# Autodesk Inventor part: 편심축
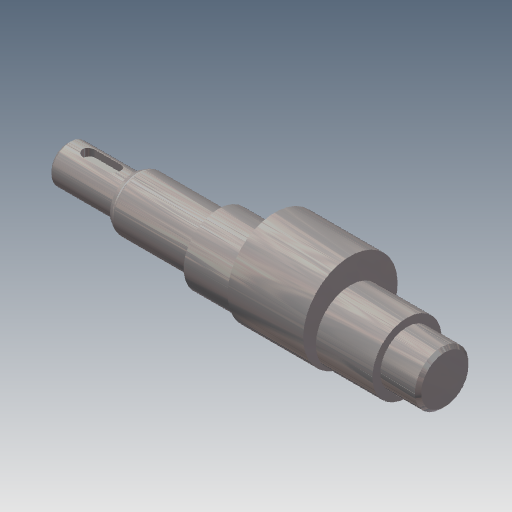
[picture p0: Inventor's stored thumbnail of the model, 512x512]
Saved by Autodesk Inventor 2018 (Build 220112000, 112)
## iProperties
Created: 2019-01
Part Number: 편심축
Material: 강철, 연강
Document SubType Name: Modeling
Designer: mduedu
Density: 7.86 g/cm^3
Appearance: 강철
Mass: 326.79 g
Surface Area: 90.9817 cm^2
Volume: 41.5764 cm^3
Author: mduedu
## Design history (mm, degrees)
sketch "스케치1"
  geometry: L1 (0, 0)-(21, 0); L2 (21, 0)-(21, 6); L3 (21, 6)-(0, 6); L4 (0, 6)-(0, 0); L5 (21, 0)-(48, 0); L6 (48, 0)-(48, 8.5); L7 (48, 8.5)-(21, 8.5); L8 (21, 8.5)-(21, 0); L9 (48, 0)-(108, 0); L10 (108, 0)-(108, 11); L11 (108, 11)-(48, 11); L12 (48, 11)-(48, 0); L13 (108, 0)-(120, 0); L14 (120, 0)-(120, 8.5); L15 (120, 8.5)-(108, 8.5); L16 (108, 8.5)-(108, 0)
  constraints: 32 end point, 8 parallel, 4 horizontal, 4 perpendicular
  dimensions: "d0" = 120 distance between parallel lines of L14 L4; "d2" = 12 distance of L14.end L15.end; "d3" = 60 distance of L10.end L11.end; "d4" = 99 distance between parallel lines of L8 L14; "d5" = 12 diameter of L3 L1; "d6" = 17 diameter of L7 L5; "d7" = 17 diameter of L15 L13; "d8" = 22 diameter of L11 L9
revolve "회전1" sketch "스케치1" stored, may be unused: angle "d9" = 90 deg
node "작업 평면1"
sketch "스케치2"
  geometry: C1 r 15 at (0, 4); C2 r 11 at (0, 0) reference; 1 further point
  constraints: 1 centre point, 1 tangent, 1 vertical alignment
  dimensions: "d11" = 4 distance of point (0, 0) C1.centre
extrude "돌출1" join sketch "스케치2" distance "d12" = 24; taper "d13" = 0 deg
node "작업 평면2"
sketch "스케치3" dims "d16" = 12
  geometry: L1 (-4.5, 2)-(3.5, 2); L2 (3.5, 2)-(3.5, -2); L3 (3.5, -2)-(-4.5, -2); L4 (-4.5, -2)-(-4.5, 2); L5 (-10.5, 8.5)-(-10.5, -8.5) reference; 3 further points
  constraints: 8 end point, 2 midpoint, 2 parallel, 2 vertical alignment, 1 horizontal, 1 horizontal alignment, 1 perpendicular, 4 other
  dimensions: "d14" = 4 distance between parallel lines of L3 L1; "d17" = 4 dimension on L5
extrude "돌출2" cut sketch "스케치3" distance "d18" = 2.5; taper "d19" = 0 deg
chamfer "모따기1" distance "d20" = 1.82; stored, may be unused: second distance "d21" = 2, angle "d22" = 30 deg
fillet "모깎기1" dims "d23" = 2
hole "구멍2" diameter "d39" = 3.242; stored, may be unused: countersink angle "d43" = 60 deg, drill point angle "d45" = 118 deg; dims "d37" = 10, "d38" = 10, "d40" = 8, "d41" = 5.51, "d42" = 2, "d44" = 10
sketch "스케치5"
  geometry: L1 (0, 0)-(2, 0); L2 (2, 0)-(2, 1.621); L3 (0, 2.776)-(0, 0); L4 (0, 2.776)-(2, 1.621); L5 (10, 1.621)-(0, 1.621) reference
  constraints: 8 end point, 1 horizontal, 1 parallel, 1 perpendicular, 1 point on line
  dimensions: "d46" = 2 distance between parallel lines of L2 L3; "d48" = 30 deg angle of L4 L1
revolve "회전2" sketch "스케치5" stored, may be unused: angle "d50" = 90 deg
chamfer "모따기2" distance "d25" = 1; stored, may be unused: second distance "d26" = 2, angle "d27" = 30 deg
node "솔리드1"
